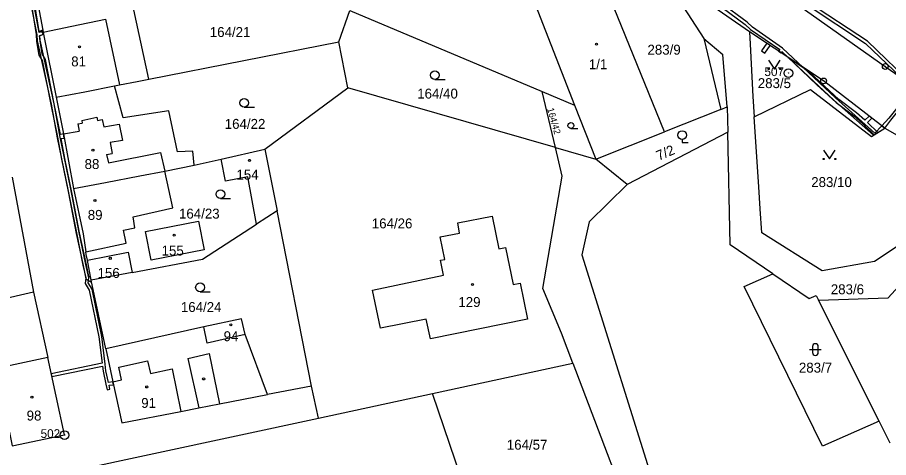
# Model space of a CAD drawing. Extents: x -779723 to -777378, y -1011169 to -1009297.
# Drawn here: x -779372 to -779222.9, y -1010276.4 to -1010201 of the extents above; entities that cross this region are included whole.
import ezdxf

# ---------------------------------------------------------------- set-up
doc = ezdxf.new("R2010")
doc.units = 0
for name, color, linetype in [('Hranice parcel', 7, 'Continuous'), ('Parcelní čísla', 7, 'Continuous'), ('Vnitřní kresba', 7, 'Continuous'), ('Věcná břemena k části', 7, 'Continuous'), ('Značky bodu BP', 7, 'Continuous'), ('Značky budov', 7, 'Continuous'), ('Značky kultur', 7, 'Continuous')]:
    doc.layers.add(name, color=color, linetype=linetype)

msp = doc.modelspace()

# ---------------------------------------------------------------- linework, layer by layer
at = {"layer": 'Hranice parcel'}
for p, q in [((-779261.29, -1010220.59), (-779273.57, -1010190.29)), ((-779285.33, -1010193.87), (-779276.66, -1010216.01)), ((-779246.71, -1010203.46), (-779262.24, -1010192.63)), ((-779349.54, -1010211.54), (-779352.97, -1010195.83)), ((-779317, -1010205.16), (-779315.16, -1010199.77)), ((-779315.16, -1010199.77), (-779282.2, -1010213.67)), ((-779349.54, -1010211.54), (-779317, -1010205.16)), ((-779315.47, -1010213.01), (-779317, -1010205.16)), ((-779329.68, -1010223.56), (-779315.47, -1010213.01)), ((-779279.96, -1010223.28), (-779315.47, -1010213.01)), ((-779282.2, -1010213.67), (-779276.66, -1010216.01)), ((-779279.96, -1010223.28), (-779282.2, -1010213.67)), ((-779276.66, -1010216.01), (-779273.03, -1010225.28)), ((-779251.62, -1010216.72), (-779261.29, -1010220.59)), ((-779273.03, -1010225.28), (-779261.29, -1010220.59)), ((-779250.45, -1010220.64), (-779267.64, -1010229.61)), ((-779337.17, -1010225.23), (-779329.68, -1010223.56)), ((-779329.68, -1010223.56), (-779327.59, -1010234.13)), ((-779279.96, -1010223.28), (-779273.03, -1010225.28)), ((-779341.78, -1010226.26), (-779337.17, -1010225.23)), ((-779336.4, -1010229.03), (-779337.17, -1010225.23)), ((-779267.64, -1010229.61), (-779273.03, -1010225.28)), ((-779346.83, -1010227.29), (-779341.78, -1010226.26)), ((-779372.96, -1010228.31), (-779369.26, -1010248.05)), ((-779345.41, -1010233.6), (-779346.83, -1010227.29)), ((-779332.59, -1010228.29), (-779336.4, -1010229.03)), ((-779331.1, -1010236.4), (-779332.59, -1010228.29)), ((-779327.59, -1010234.13), (-779331.1, -1010236.4)), ((-779321.68, -1010264.11), (-779327.59, -1010234.13)), ((-779360.33, -1010241.1), (-779353.42, -1010239.67)), ((-779359.42, -1010245.98), (-779360.07, -1010242.55)), ((-779352.38, -1010244.66), (-779359.42, -1010245.98)), ((-779356.9, -1010257.72), (-779359.42, -1010245.98)), ((-779369.26, -1010248.05), (-779389.34, -1010252.55)), ((-779369.26, -1010248.05), (-779366.85, -1010259.23)), ((-779224.53, -1010270.12), (-779234.91, -1010249.39)), ((-779340.13, -1010253.99), (-779356.9, -1010257.72)), ((-779329.22, -1010265.58), (-779333.07, -1010255.29)), ((-779300.99, -1010265.39), (-779276.95, -1010260.2)), ((-779321.68, -1010264.11), (-779329.22, -1010265.58)), ((-779320.52, -1010269.6), (-779321.68, -1010264.11)), ((-779320.52, -1010269.6), (-779300.99, -1010265.39)), ((-779292.43, -1010290.53), (-779300.99, -1010265.39)), ((-779222.63, -1010273.91), (-779224.53, -1010270.12))]:
    msp.add_line(p, q, dxfattribs=at)
for points in [[(-779262.24, -1010192.63), (-779254.52, -1010204.61), (-779251.62, -1010216.72)], [(-779242.79, -1010195.65), (-779223.48, -1010209.38), (-779213.39, -1010216.37), (-779205.69, -1010223.63)], [(-779368.51, -1010198.95), (-779367.68, -1010203.17), (-779367.63, -1010203.52), (-779367.55, -1010203.87), (-779365.42, -1010214.66)], [(-779223.57, -1010219.94), (-779234.04, -1010211.86), (-779246.71, -1010203.46)], [(-779246.71, -1010203.46), (-779246.59, -1010205.57), (-779246.15, -1010214.51), (-779245.92, -1010218.02)], [(-779355.42, -1010212.7), (-779354.59, -1010212.5), (-779351.55, -1010211.93), (-779349.54, -1010211.54)], [(-779365.42, -1010214.66), (-779360.52, -1010213.7), (-779355.42, -1010212.7)], [(-779341.78, -1010226.26), (-779342.02, -1010223.87), (-779344.62, -1010224.02), (-779346.13, -1010216.99), (-779353.94, -1010218.2), (-779355.42, -1010212.7)], [(-779245.92, -1010218.02), (-779236.27, -1010213.3), (-779225.85, -1010221.36), (-779223.57, -1010219.94)], [(-779365.42, -1010214.66), (-779364.16, -1010220.93), (-779362.43, -1010230.27)], [(-779251.62, -1010216.72), (-779250.54, -1010216.27), (-779250.45, -1010220.64)], [(-779213.22, -1010230.72), (-779219.59, -1010238.93), (-779225.31, -1010242.76), (-779234.3, -1010244.39), (-779244.61, -1010237.88), (-779244.88, -1010233.78), (-779245.13, -1010229.97), (-779245.92, -1010218.02)], [(-779242.75, -1010244.88), (-779250.04, -1010239.9), (-779250.45, -1010220.64)], [(-779223.57, -1010219.94), (-779216.54, -1010223.96), (-779213.22, -1010230.72)], [(-779276.95, -1010260.2), (-779278.89, -1010255.08), (-779282.1, -1010247.39), (-779278.82, -1010228.15), (-779279.96, -1010223.28)], [(-779362.43, -1010230.27), (-779356.99, -1010229.23), (-779351.1, -1010228.1), (-779346.83, -1010227.29)], [(-779267.64, -1010229.61), (-779274.18, -1010236), (-779275.45, -1010241.64), (-779248.83, -1010326.61)], [(-779362.43, -1010230.27), (-779360.81, -1010238.06), (-779360.33, -1010241.1)], [(-779353.42, -1010239.67), (-779353.88, -1010237.43), (-779351.94, -1010237.03), (-779352.2, -1010235.13), (-779345.41, -1010233.6)], [(-779299.63, -1010242.58), (-779298.86, -1010242.42), (-779299.67, -1010238.58), (-779296.34, -1010237.93), (-779296.68, -1010236.16), (-779290.77, -1010235.01), (-779289.63, -1010240.6), (-779288.47, -1010240.36), (-779287.16, -1010246.73), (-779285.99, -1010246.49), (-779284.72, -1010252.66), (-779301.34, -1010256.04), (-779302.06, -1010252.64), (-779309.89, -1010254.22), (-779311.24, -1010247.7), (-779299.09, -1010245.15), (-779299.63, -1010242.58)], [(-779234.91, -1010249.39), (-779222.98, -1010249.03), (-779210.79, -1010235.65)], [(-779352.38, -1010244.66), (-779340.34, -1010242.39), (-779331.1, -1010236.4)], [(-779350.1, -1010237.63), (-779341.04, -1010235.87), (-779340.09, -1010240.76), (-779349.15, -1010242.54), (-779350.1, -1010237.63)], [(-779360.07, -1010242.55), (-779360.26, -1010241.57), (-779360.33, -1010241.1)], [(-779360.07, -1010242.55), (-779353.08, -1010241.18), (-779352.38, -1010244.66)], [(-779224.53, -1010270.12), (-779234.22, -1010274.39), (-779247.62, -1010247.08), (-779242.75, -1010244.88)], [(-779242.75, -1010244.88), (-779236.53, -1010249.13), (-779235.31, -1010248.59), (-779234.91, -1010249.39)], [(-779333.07, -1010255.29), (-779333.7, -1010252.59), (-779340.13, -1010253.99)], [(-779333.07, -1010255.29), (-779339.57, -1010256.76), (-779340.13, -1010253.99)], [(-779356.9, -1010257.72), (-779355.68, -1010263.39), (-779354.17, -1010270.43), (-779344.05, -1010268.46), (-779341.01, -1010267.87), (-779337.47, -1010267.18), (-779329.22, -1010265.58)], [(-779366.85, -1010259.23), (-779375.67, -1010261.12), (-779372.96, -1010274.36)], [(-779372.96, -1010274.36), (-779363.99, -1010272.5), (-779366.85, -1010259.23)], [(-779276.95, -1010260.2), (-779264.13, -1010293.98), (-779263.36, -1010296.74)], [(-779411.57, -1010289.24), (-779362.78, -1010278.71), (-779320.52, -1010269.6)]]:
    msp.add_lwpolyline(points, dxfattribs=at)
at = {"layer": 'Vnitřní kresba'}
for p, q in [((-779362.74, -1010202.49), (-779356.94, -1010201.26)), ((-779356.94, -1010201.26), (-779354.59, -1010212.5)), ((-779367.63, -1010203.52), (-779362.74, -1010202.49)), ((-779254.52, -1010204.61), (-779251.28, -1010207.31)), ((-779250.54, -1010216.27), (-779251.28, -1010207.31)), ((-779361.69, -1010219.18), (-779360.95, -1010219.06)), ((-779361.69, -1010219.18), (-779361.45, -1010220.46)), ((-779361.03, -1010218.61), (-779358.43, -1010218.07)), ((-779361.03, -1010218.61), (-779360.95, -1010219.06)), ((-779358.43, -1010218.07), (-779358.32, -1010218.61)), ((-779358.32, -1010218.61), (-779357.53, -1010218.47)), ((-779357.53, -1010218.47), (-779357.27, -1010219.74)), ((-779357.27, -1010219.74), (-779354.61, -1010219.28)), ((-779354.61, -1010219.28), (-779354.07, -1010222.04)), ((-779364.16, -1010220.93), (-779361.45, -1010220.46)), ((-779354.07, -1010222.04), (-779356.19, -1010222.38)), ((-779356.19, -1010222.38), (-779355.84, -1010224.3)), ((-779356.77, -1010224.47), (-779355.84, -1010224.3)), ((-779356.77, -1010224.47), (-779356.45, -1010225.88)), ((-779356.45, -1010225.88), (-779347.53, -1010224.13)), ((-779347.53, -1010224.13), (-779346.83, -1010227.29)), ((-779342.88, -1010259.37), (-779339.21, -1010258.56)), ((-779342.88, -1010259.37), (-779341.01, -1010267.87)), ((-779339.21, -1010258.56), (-779337.47, -1010267.18)), ((-779354.69, -1010260.87), (-779349.8, -1010259.81)), ((-779354.22, -1010263.07), (-779354.69, -1010260.87)), ((-779349.8, -1010259.81), (-779349.27, -1010261.99)), ((-779349.27, -1010261.99), (-779345.55, -1010261.19)), ((-779345.55, -1010261.19), (-779344.05, -1010268.46)), ((-779355.68, -1010263.39), (-779354.22, -1010263.07))]:
    msp.add_line(p, q, dxfattribs=at)
at = {"layer": 'Věcná břemena k části'}
for points in [[(-779256.41, -1010195.49), (-779247.46, -1010202.19), (-779246.55, -1010203.03), (-779241.56, -1010206.49), (-779241.74, -1010206.76), (-779241.32, -1010207.03), (-779241.17, -1010206.81), (-779240.13, -1010207.82), (-779237.54, -1010209.54), (-779241.06, -1010206.23), (-779246.23, -1010202.63), (-779247.14, -1010201.81), (-779256.12, -1010195.09)], [(-779369.66, -1010199.07), (-779368.73, -1010203.94), (-779368.64, -1010204.96), (-779366.24, -1010215.85), (-779365.24, -1010221.61), (-779363.45, -1010230.15), (-779361.94, -1010237.9), (-779360.82, -1010243.41), (-779360.33, -1010245.59), (-779360.44, -1010246.53), (-779359.74, -1010247.69), (-779358.1, -1010255.7), (-779357.56, -1010260.21), (-779366.25, -1010262.02), (-779366.15, -1010262.5), (-779357.5, -1010260.71), (-779357.39, -1010261.59), (-779356.9, -1010263.81), (-779356.69, -1010264.75), (-779356.21, -1010264.65), (-779356.36, -1010263.97), (-779355.58, -1010263.88), (-779355.68, -1010263.39), (-779356.46, -1010263.48), (-779356.89, -1010261.51), (-779357.03, -1010260.38), (-779357.61, -1010255.62), (-779359.26, -1010247.51), (-779359.92, -1010246.41), (-779359.83, -1010245.57), (-779360.34, -1010243.31), (-779361.45, -1010237.81), (-779362.96, -1010230.06), (-779364.74, -1010221.51), (-779365.74, -1010215.75), (-779368.14, -1010204.88), (-779368.22, -1010204.07), (-779367.57, -1010203.82), (-779367.86, -1010203.38), (-779368.3, -1010203.56), (-779369.17, -1010198.98)], [(-779369.64, -1010198.88), (-779368.86, -1010203.88), (-779368.75, -1010205.09), (-779368.39, -1010207.45), (-779367.78, -1010208.38), (-779366.33, -1010215.87), (-779365.2, -1010221.5), (-779364.49, -1010225.28), (-779363.32, -1010231.09), (-779361.98, -1010237.97), (-779360.78, -1010243.47), (-779360.35, -1010245.74), (-779359.34, -1010246.35), (-779359.42, -1010245.98), (-779359.5, -1010245.55), (-779359.81, -1010245.36), (-779360.2, -1010243.35), (-779361.4, -1010237.85), (-779362.74, -1010230.97), (-779363.91, -1010225.16), (-779364.55, -1010221.73), (-779364.03, -1010221.64), (-779364.16, -1010220.93), (-779364.68, -1010221.04), (-779365.75, -1010215.75), (-779367.22, -1010208.16), (-779367.81, -1010207.23), (-779368.15, -1010205.01), (-779368.24, -1010204.1), (-779367.55, -1010203.87), (-779367.63, -1010203.52), (-779367.68, -1010203.17), (-779368.33, -1010203.39), (-779369.04, -1010198.78)]]:
    msp.add_lwpolyline(points, dxfattribs=at)
for points in [[(-779220.81, -1010211.23), (-779218.5, -1010212.83), (-779226.54, -1010205.05), (-779236.62, -1010198.39), (-779242.2, -1010195.65), (-779242.79, -1010195.65), (-779241.36, -1010196.66), (-779236.86, -1010198.82), (-779226.86, -1010205.45)], [(-779244.68, -1010206.71), (-779244.1, -1010207.11), (-779243.19, -1010205.79), (-779243.78, -1010205.4)], [(-779223.57, -1010219.94), (-779224.1, -1010219.53), (-779225.26, -1010220.78), (-779231.98, -1010214.77), (-779237.54, -1010209.54), (-779240.13, -1010207.82), (-779232.31, -1010215.13), (-779225.51, -1010221.15)], [(-779225.38, -1010221.07), (-779224.77, -1010220.69), (-779226.55, -1010218.96), (-779225.76, -1010218.25), (-779226.24, -1010217.88), (-779226.99, -1010218.55), (-779228.41, -1010217.3), (-779231.45, -1010215.01), (-779234.71, -1010212.01), (-779236.8, -1010210.03), (-779240.13, -1010207.82), (-779239.01, -1010208.89), (-779235.19, -1010212.53), (-779231.89, -1010215.55), (-779228.85, -1010217.84), (-779227.27, -1010219.24)], [(-779218.14, -1010213.08), (-779218.5, -1010212.83), (-779219.41, -1010212.2), (-779219.92, -1010211.85), (-779220.81, -1010211.23), (-779218.81, -1010213.14), (-779222.9, -1010218.24), (-779224.1, -1010219.53), (-779223.57, -1010219.94), (-779222.52, -1010218.56)]]:
    msp.add_lwpolyline(points, close=True, dxfattribs=at)
at = {"layer": 'Značky bodu BP'}
for centre, radius in [((-779223.48, -1010209.38), 0.5), ((-779240.07, -1010210.52), 0.75), ((-779223.48, -1010209.38), 0.0303), ((-779240.07, -1010210.52), 0.03), ((-779234.04, -1010211.86), 0.5), ((-779234.04, -1010211.86), 0.0303), ((-779363.97, -1010272.51), 0.75), ((-779363.97, -1010272.51), 0.03)]:
    msp.add_circle(centre, radius, dxfattribs=at)
at = {"layer": 'Značky budov'}
for centre in [(-779361.4, -1010206.03), (-779272.92, -1010205.57), (-779359.11, -1010223.72), (-779332.32, -1010225.46), (-779358.77, -1010232.33), (-779345.22, -1010238.26), (-779356.14, -1010242.24), (-779294.13, -1010246.74), (-779335.5, -1010253.62), (-779349.91, -1010264.27), (-779340.16, -1010262.9), (-779369.55, -1010266.01)]:
    msp.add_circle(centre, 0.175, dxfattribs=at)
at = {"layer": 'Značky kultur'}
for p, q in [((-779300.59, -1010211.61), (-779298.84, -1010211.61)), ((-779333.22, -1010216.35), (-779331.47, -1010216.35)), ((-779277.3, -1010220), (-779276.12, -1010220)), ((-779258.25, -1010221.88), (-779258.25, -1010222.38)), ((-779258.25, -1010222.38), (-779257.25, -1010222.38)), ((-779337.29, -1010231.99), (-779335.54, -1010231.99)), ((-779340.78, -1010247.96), (-779339.03, -1010247.96)), ((-779236.45, -1010257.86), (-779234.45, -1010257.86)), ((-779235.95, -1010257.36), (-779235.95, -1010258.36)), ((-779234.95, -1010258.36), (-779234.95, -1010257.36))]:
    msp.add_line(p, q, dxfattribs=at)
for points in [[(-779243.45, -1010208.31), (-779242.45, -1010209.81), (-779241.45, -1010208.31)], [(-779234.04, -1010223.72), (-779233.04, -1010225.22), (-779232.04, -1010223.72)]]:
    msp.add_lwpolyline(points, dxfattribs=at)
for centre, radius in [((-779300.59, -1010210.86), 0.75), ((-779243.45, -1010209.81), 0.1), ((-779241.45, -1010209.81), 0.1), ((-779333.22, -1010215.6), 0.75), ((-779277.3, -1010219.5), 0.502), ((-779258.25, -1010221.13), 0.75), ((-779234.04, -1010225.22), 0.1), ((-779232.04, -1010225.22), 0.1), ((-779337.29, -1010231.24), 0.75), ((-779340.78, -1010247.21), 0.75)]:
    msp.add_circle(centre, radius, dxfattribs=at)
for centre, start, end in [((-779235.45, -1010257.36), 0, 180), ((-779235.45, -1010258.36), 180, 359.9879)]:
    msp.add_arc(centre, 0.5, start, end, dxfattribs=at)

# ---------------------------------------------------------------- texts
at = {"layer": 'Parcelní čísla'}
for s, p in [('164/21', (-779339.11, -1010204.33)), ('283/9', (-779264.19, -1010207.35)), ('81', (-779362.83, -1010209.36)), ('1/1', (-779274.23, -1010209.85)), ('283/5', (-779245.31, -1010213.08)), ('164/40', (-779303.6, -1010214.87)), ('164/22', (-779336.55, -1010220.06)), ('88', (-779360.54, -1010226.94)), ('154', (-779334.55, -1010228.76)), ('283/10', (-779236.16, -1010230.03)), ('89', (-779360, -1010235.65)), ('164/23', (-779344.38, -1010235.43)), ('164/26', (-779311.38, -1010237.11)), ('155', (-779347.36, -1010241.76)), ('156', (-779358.32, -1010245.6)), ('283/6', (-779232.81, -1010248.39)), ('129', (-779296.56, -1010250.57)), ('164/24', (-779344.06, -1010251.43)), ('94', (-779336.74, -1010256.43)), ('283/7', (-779238.27, -1010261.81)), ('91', (-779350.85, -1010267.86)), ('98', (-779370.46, -1010270.02)), ('164/57', (-779288.27, -1010275.02))]:
    msp.add_text(s, height=1.7, dxfattribs=at).set_placement(p)
for s, height, rotation, p in [('164/42', 1.14, 286, (-779281.38, -1010216.63)), ('7/2', 1.7, 23, (-779262.26, -1010225.54))]:
    msp.add_text(s, height=height, rotation=rotation, dxfattribs=at).set_placement(p)
at = {"layer": 'Značky bodu BP'}
for s, p in [('507', (-779244.17, -1010211.02)), ('502', (-779368.07, -1010273.01))]:
    msp.add_text(s, height=1.5, dxfattribs=at).set_placement(p)

doc.saveas('drawing.dxf')
